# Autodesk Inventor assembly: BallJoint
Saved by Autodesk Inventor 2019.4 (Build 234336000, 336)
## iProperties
Created: 2020-02
Part Number: BallJoint
Document SubType Name: Assembly
Designer: Administrator
Title: BallJoint v14
Author: Administrator
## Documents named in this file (3)
- c:\worker\convert-fusion-r01\tmp\job-1\5\output\files\e4333473-a38b-4431-9958-ad24a2f67704\BallJoint v14_2.iam
- c:\worker\convert-fusion-r01\tmp\job-1\5\output\files\e4333473-a38b-4431-9958-ad24a2f67704\Component1_1.ipt
- c:\worker\convert-fusion-r01\tmp\job-1\5\output\files\e4333473-a38b-4431-9958-ad24a2f67704\Component2_1.ipt
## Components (2 placed, 2 different names)
1. Component1:1
2. Component2:1
